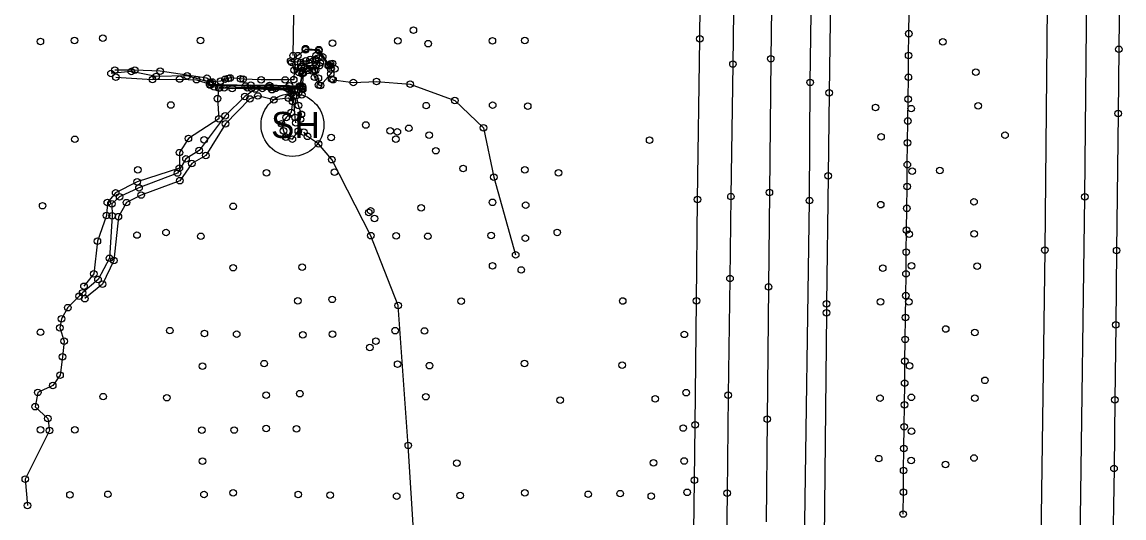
# Model space of a CAD drawing. Extents: x 20503438 to 20508873, y 7964251 to 7984667.
# Drawn here: x 20506435.8 to 20506772.2, y 7973039.7 to 7973190.9 of the extents above; entities that cross this region are included whole.
import ezdxf

# ---------------------------------------------------------------- set-up
doc = ezdxf.new("R2010")
doc.units = 0
for name, color, linetype in [('SurBreakLine', 7, 'Continuous'), ('SurConcreteSlab', 7, 'Continuous'), ('SurDrainageArrowDown', 7, 'Continuous'), ('SurDrainageArrowUp', 7, 'Continuous'), ('SurEdgeRoadPaved', 7, 'Continuous'), ('SurEdgeShoulderPaved', 7, 'Continuous'), ('SurGuardPost', 7, 'Continuous'), ('SurNaturalCells', 7, 'Continuous'), ('SurPointsNonDTM', 7, 'Continuous'), ('SurSurveyPoints', 7, 'Continuous')]:
    doc.layers.add(name, color=color, linetype=linetype)

msp = doc.modelspace()

# ---------------------------------------------------------------- linework, layer by layer
at = {"layer": 'SurBreakLine'}
for points in [[(20506693.93, 7974172.3), (20506703.16, 7974103.94), (20506708.65, 7974061.23), (20506717.15, 7973987.75), (20506724.71, 7973915.62), (20506727.66, 7973879.07), (20506730.35, 7973842.27), (20506733.65, 7973807.54), (20506740.64, 7973700.69), (20506742.76, 7973663.23), (20506744.46, 7973628.25), (20506747.41, 7973556.42), (20506749.27, 7973483.89), (20506749.75, 7973448.34), (20506750.05, 7973411.41), (20506750.05, 7973377.87), (20506750.04, 7973336.11), (20506749.88, 7973302.38), (20506749.66, 7973266.92), (20506748.75, 7973195.65), (20506748.06, 7973121.35), (20506742.68, 7972730.78)], [(20506658.64, 7973666.41), (20506660.5, 7973630.6), (20506663.28, 7973558.51), (20506664.28, 7973522.31), (20506665.15, 7973486.02), (20506665.41, 7973468.23), (20506665.94, 7973428.1), (20506666.1, 7973414.15), (20506666.08, 7973375.19), (20506665.8, 7973329.98), (20506665.6, 7973292.94), (20506665.39, 7973261.91), (20506665.32, 7973236.07), (20506664.68, 7973202.81), (20506664.37, 7973179.69), (20506663.97, 7973138.88), (20506663.74, 7973110.09), (20506663.33, 7973069.8), (20506662.94, 7973038.47)], [(20506522.96, 7973176.73), (20506524.98, 7973176.27), (20506526.63, 7973177.56), (20506526.85, 7973178.46), (20506526.35, 7973179.85), (20506525.65, 7973180.7), (20506523.8, 7973179.43), (20506520.91, 7973178.53), (20506520.17, 7973177.11), (20506520.35, 7973175.54), (20506521.34, 7973175.08)], [(20506518.16, 7973178.53), (20506518.9, 7973176.23), (20506518.77, 7973173.3), (20506516.16, 7973173.21), (20506508.85, 7973173.26), (20506503.37, 7973173.49), (20506502.57, 7973173.56), (20506499.34, 7973173.81), (20506498.72, 7973173.66), (20506497.8, 7973173.43), (20506496.43, 7973172.86), (20506493.91, 7973172.6), (20506492.3, 7973173.75), (20506477.98, 7973175.87), (20506470.27, 7973176.19), (20506464.13, 7973176.18)], [(20506521.69, 7973175.3), (20506523.09, 7973176.09), (20506524.37, 7973175.97), (20506525.13, 7973174.02), (20506526.3, 7973173.77), (20506526.31, 7973171.68), (20506526.93, 7973171.55), (20506530.06, 7973175.09), (20506531.32, 7973176.62), (20506530.58, 7973178.27), (20506529.6, 7973177.45)], [(20506464.51, 7973174.08), (20506475.68, 7973173.34), (20506483.96, 7973173.49), (20506489.08, 7973173.3), (20506493.12, 7973171.91), (20506505.64, 7973171.61)], [(20506496.15, 7973170.84), (20506497.55, 7973170.77), (20506500.01, 7973170.63), (20506505.91, 7973170.66), (20506509.19, 7973170.6), (20506513.19, 7973170.66), (20506516.65, 7973170.71), (20506521.52, 7973170.42), (20506521.69, 7973175.3)], [(20506521.34, 7973175.08), (20506520.56, 7973171.34), (20506517.52, 7973171.45), (20506511.33, 7973171.52), (20506505.64, 7973171.61)], [(20506496.15, 7973170.84), (20506495.95, 7973170.71), (20506495.49, 7973167.51), (20506495.9, 7973161.36), (20506486.62, 7973155.34), (20506483.93, 7973151.05), (20506483.86, 7973146.29), (20506470.96, 7973142.15), (20506464.42, 7973138.77), (20506461.88, 7973135.81), (20506461.59, 7973131.9), (20506458.84, 7973124.03), (20506457.76, 7973114.06), (20506454.75, 7973110.29)], [(20506518.36, 7973166.67), (20506517.16, 7973167.66), (20506512.67, 7973167.11), (20506507.85, 7973168.33), (20506505.42, 7973167.42), (20506497.98, 7973159.86), (20506491.97, 7973150.16), (20506487.69, 7973147.73), (20506483.98, 7973142.5), (20506472.18, 7973138.12), (20506467.71, 7973135.8), (20506465.25, 7973131.52), (20506463.87, 7973118.15), (20506460.39, 7973110.95), (20506454.98, 7973106.52)]]:
    msp.add_lwpolyline(points, dxfattribs=at)
for points in [[(20506521.37, 7973176.11), (20506523.67, 7973177.61), (20506525.7, 7973177.77), (20506525.43, 7973179.03), (20506523.53, 7973178.28), (20506520.99, 7973177.32)], [(20506515.63, 7973157.68), (20506516.37, 7973155.74), (20506518.35, 7973155.18), (20506520.17, 7973157.59), (20506520.86, 7973161.22), (20506521.11, 7973162.73), (20506520.23, 7973165.41), (20506519.61, 7973168.45), (20506521.27, 7973168.66), (20506521.45, 7973170.42), (20506520, 7973170.37), (20506518.16, 7973170.4), (20506518.11, 7973169.03), (20506518.36, 7973166.67), (20506518, 7973163.27), (20506516.49, 7973161.74), (20506515.08, 7973159.84)]]:
    msp.add_lwpolyline(points, close=True, dxfattribs=at)
at = {"layer": 'SurConcreteSlab'}
for points in [[(20506522.34, 7973182.75), (20506526.47, 7973182.46), (20506529.52, 7973177.7), (20506530, 7973178.08)], [(20506529.33, 7973177.59), (20506527.61, 7973180.27), (20506526.45, 7973182.14), (20506522.39, 7973182.41), (20506520.07, 7973180.63), (20506517.83, 7973178.98), (20506519.89, 7973178.74), (20506522.5, 7973179.05)], [(20506525.4, 7973176.09), (20506522.96, 7973176.68), (20506521.5, 7973175.42), (20506520.75, 7973171.38), (20506521.38, 7973171.31), (20506521.49, 7973171.14), (20506521.37, 7973170.6), (20506511.53, 7973170.91), (20506504.61, 7973170.78), (20506494.46, 7973171.12), (20506493.3, 7973171.62), (20506504, 7973171.37), (20506511.47, 7973171.43), (20506520.65, 7973171.12)]]:
    msp.add_lwpolyline(points, dxfattribs=at)
at = {"layer": 'SurDrainageArrowDown'}
for points in [[(20506704.79, 7973040.84), (20506704.87, 7973047.5), (20506704.95, 7973054.15), (20506705.03, 7973060.81), (20506705.11, 7973067.47), (20506705.19, 7973074.13), (20506705.27, 7973080.79), (20506705.35, 7973087.45), (20506705.44, 7973094.11), (20506705.52, 7973100.77), (20506705.6, 7973107.43), (20506705.68, 7973114.09), (20506705.76, 7973120.74), (20506705.84, 7973127.4), (20506705.92, 7973134.06), (20506706, 7973140.72), (20506706.08, 7973147.38), (20506706.16, 7973154.04), (20506706.24, 7973160.7), (20506706.32, 7973167.36), (20506706.4, 7973174.02), (20506706.48, 7973180.68), (20506706.56, 7973187.33), (20506706.64, 7973193.99)], [(20506519.44, 7973160.13), (20506519.18, 7973161.79), (20506518.68, 7973168.3), (20506518.97, 7973169.93)], [(20506582.39, 7972475.07), (20506582.65, 7972516.36), (20506588.45, 7972561.12), (20506586.2, 7972602.19), (20506585.43, 7972649.8), (20506585.69, 7972698.55), (20506585.31, 7972750.39), (20506584.27, 7972792.42), (20506582.67, 7972835.44), (20506573.89, 7972881.78), (20506561.94, 7972896), (20506559.1, 7972961.09), (20506557.3, 7973005.18), (20506553.75, 7973061.78), (20506550.66, 7973104.43), (20506542.34, 7973125.73), (20506530.42, 7973148.91), (20506526.31, 7973153.75), (20506522.97, 7973156.02), (20506521.88, 7973157.28)]]:
    msp.add_lwpolyline(points, dxfattribs=at)
at = {"layer": 'SurDrainageArrowUp'}
for points in [[(20506493.28, 7973172.48), (20506486.24, 7973174.47), (20506476.82, 7973174.29), (20506469.2, 7973175.79), (20506463, 7973175.19)], [(20506530.36, 7973173.49), (20506530.78, 7973173.29), (20506536.97, 7973172.44), (20506544.08, 7973172.74), (20506554.36, 7973171.96), (20506567.98, 7973166.95), (20506576.73, 7973158.64), (20506579.89, 7973143.58), (20506586.52, 7973119.89)], [(20506517.46, 7973170.19), (20506512.14, 7973170.24), (20506507.02, 7973170.45), (20506503.84, 7973168.2), (20506497.87, 7973162.27), (20506489.92, 7973151.73), (20506485.89, 7973149.13), (20506483.27, 7973144.83), (20506471.54, 7973140.28), (20506465.63, 7973137.57), (20506463.27, 7973135.47), (20506463.32, 7973131.8), (20506462.52, 7973118.83), (20506459.03, 7973112.33), (20506454.34, 7973108.32), (20506453.3, 7973107.31), (20506449.85, 7973103.78), (20506447.91, 7973100.39), (20506447.39, 7973097.64), (20506448.69, 7973093.53), (20506448.16, 7973088.79), (20506447.44, 7973083.19), (20506445.2, 7973080.07), (20506440.68, 7973077.94), (20506439.84, 7973073.58), (20506443.73, 7973069.96), (20506444.23, 7973066.33), (20506436.84, 7973051.49), (20506437.54, 7973043.48)]]:
    msp.add_lwpolyline(points, dxfattribs=at)
at = {"layer": 'SurEdgeRoadPaved'}
for points in [[(20506754.96, 7972745.65), (20506760.25, 7973137.58), (20506761.69, 7973282.93), (20506761.86, 7973353.9), (20506761.6, 7973424.82), (20506761.25, 7973458.85), (20506759.99, 7973532.54), (20506759.04, 7973564.75), (20506756.04, 7973636.58), (20506754.65, 7973665.96), (20506750.79, 7973733.72), (20506746.15, 7973800.82), (20506743.33, 7973835.58), (20506740.64, 7973867.92), (20506734.47, 7973936.28), (20506730.78, 7973972.39), (20506727.6, 7974001.68), (20506722.88, 7974042.92), (20506713.77, 7974114.92), (20506708.86, 7974151.42)], [(20506762.7, 7973701.3), (20506766.3, 7973628.52), (20506769.13, 7973555.56), (20506770.34, 7973519.36), (20506770.9, 7973482.77), (20506771.77, 7973445.1), (20506772.21, 7973371.49), (20506772.15, 7973360.12), (20506771.84, 7973291.7), (20506771.22, 7973237.95), (20506770.63, 7973182.56), (20506770.42, 7973162.97), (20506769.97, 7973121.19), (20506769.69, 7973098.56), (20506769.4, 7973075.66), (20506769.17, 7973054.72), (20506768.76, 7973026.07)], [(20506647.01, 7973660.24), (20506649.17, 7973617.44), (20506650.75, 7973577.56), (20506651.82, 7973545.13), (20506652.82, 7973509.46), (20506653.66, 7973463.03), (20506654.08, 7973436.98), (20506654.43, 7973400.6), (20506654.36, 7973389.39), (20506654.26, 7973372.56), (20506653.85, 7973322.78), (20506653.8, 7973301.82), (20506653.6, 7973256.77), (20506653.38, 7973225.81), (20506652.86, 7973178.07), (20506652.25, 7973137.64), (20506651.95, 7973112.67), (20506651.39, 7973077.12), (20506651.1, 7973047.21), (20506650.35, 7972994.14)], [(20506674.66, 7973031.32), (20506676.22, 7973136.41), (20506676.43, 7973172.48), (20506676.95, 7973207.59), (20506676.91, 7973240.58), (20506677.3, 7973275.95), (20506677.43, 7973310.72), (20506677.78, 7973346.61), (20506677.91, 7973379.86), (20506677.82, 7973415.88), (20506676.91, 7973485.63), (20506676.13, 7973520.88), (20506674, 7973590.15), (20506670.75, 7973659.42)], [(20506640.4, 7972996.37), (20506641.08, 7973051.14), (20506641.29, 7973068.03), (20506641.72, 7973105.85), (20506642.04, 7973136.76), (20506642.75, 7973185.74), (20506643.15, 7973227), (20506643.5, 7973266.97), (20506643.74, 7973295.62), (20506643.83, 7973313.1), (20506643.84, 7973316.04), (20506644.07, 7973368.4), (20506644.24, 7973389.25), (20506644.31, 7973418.66), (20506643.92, 7973441.49), (20506643.48, 7973476.06), (20506642.99, 7973504.63), (20506642.72, 7973513.53), (20506641.84, 7973543.02), (20506640.28, 7973592.41), (20506639.45, 7973610.26), (20506637.61, 7973650.43)]]:
    msp.add_lwpolyline(points, dxfattribs=at)
at = {"layer": 'SurEdgeShoulderPaved'}
msp.add_lwpolyline([(20506630.34, 7974152.37), (20506635.51, 7974114.13), (20506640.28, 7974077.28), (20506644.45, 7974039.3), (20506649.14, 7974001.32), (20506656.18, 7973935.68), (20506657.87, 7973918.76), (20506662.74, 7973866.45), (20506666.67, 7973820.29), (20506669.36, 7973783.88), (20506674.48, 7973709.53), (20506680.04, 7973598.16), (20506681.26, 7973562.05), (20506683.25, 7973489.61), (20506683.95, 7973452.45), (20506684.17, 7973413.27), (20506684.21, 7973379.49), (20506683.74, 7973332.17), (20506683.17, 7973234.7), (20506682.2, 7973169.26), (20506681.89, 7973143.95), (20506681.42, 7973104.97), (20506681.39, 7973102.17), (20506680.61, 7973023.61)], dxfattribs=at)
at = {"layer": 'SurGuardPost'}
msp.add_lwpolyline([(20506518.56, 7973180.63), (20506518.94, 7973199.21), (20506518.88, 7973206.16)], dxfattribs=at)
at = {"layer": 'SurNaturalCells'}
msp.add_circle((20506518.38, 7973159.49), 9.59, dxfattribs=at)
at = {"layer": 'SurPointsNonDTM'}
for centre in [(20506555.3, 7973188.4), (20506518.56, 7973180.63), (20506540.81, 7973159.48), (20506553.93, 7973158.47), (20506548.22, 7973157.71), (20506550.4, 7973157.39), (20506560.15, 7973156.37), (20506562.16, 7973151.64), (20506541.66, 7973132.77), (20506542.26, 7973133.27), (20506557.66, 7973134.21), (20506543.42, 7973130.97), (20506558.71, 7973096.67), (20506542.04, 7973091.64), (20506543.88, 7973093.54)]:
    msp.add_circle(centre, 1, dxfattribs=at)
at = {"layer": 'SurSurveyPoints'}
for centre in [(20506451.85, 7973185.25), (20506460.52, 7973185.96), (20506490.32, 7973185.24), (20506550.58, 7973185.17), (20506579.41, 7973185.15), (20506589.3, 7973185.22), (20506642.75, 7973185.74), (20506706.56, 7973187.33), (20506441.44, 7973184.96), (20506522.34, 7973182.75), (20506522.39, 7973182.41), (20506526.45, 7973182.14), (20506526.47, 7973182.46), (20506530.59, 7973184.42), (20506559.8, 7973184.28), (20506716.9, 7973184.81), (20506770.63, 7973182.56), (20506517.83, 7973178.98), (20506518.16, 7973178.53), (20506519.89, 7973178.74), (20506520.07, 7973180.63), (20506520.91, 7973178.53), (20506522.5, 7973179.05), (20506523.53, 7973178.28), (20506523.8, 7973179.43), (20506525.43, 7973179.03), (20506525.65, 7973180.7), (20506526.35, 7973179.85), (20506526.85, 7973178.46), (20506527.61, 7973180.27), (20506664.37, 7973179.69), (20506706.48, 7973180.68), (20506463, 7973175.19), (20506464.13, 7973176.18), (20506469.2, 7973175.79), (20506470.27, 7973176.19), (20506477.98, 7973175.87), (20506518.9, 7973176.23), (20506520.17, 7973177.11), (20506520.35, 7973175.54), (20506520.99, 7973177.32), (20506521.34, 7973175.08), (20506521.37, 7973176.11), (20506521.5, 7973175.42), (20506521.69, 7973175.3), (20506522.96, 7973176.73), (20506522.96, 7973176.68), (20506523.09, 7973176.09), (20506523.67, 7973177.61), (20506524.37, 7973175.97), (20506524.98, 7973176.27), (20506525.4, 7973176.09), (20506525.7, 7973177.77), (20506526.63, 7973177.56), (20506529.33, 7973177.59), (20506529.52, 7973177.7), (20506529.6, 7973177.45), (20506530, 7973178.08), (20506530.06, 7973176.52), (20506530.06, 7973175.09), (20506530.58, 7973178.27), (20506531.32, 7973176.62), (20506652.86, 7973178.07), (20506726.97, 7973175.57), (20506464.51, 7973174.08), (20506475.68, 7973173.34), (20506476.82, 7973174.29), (20506483.96, 7973173.49), (20506486.24, 7973174.47), (20506489.08, 7973173.3), (20506492.3, 7973173.75), (20506493.12, 7973171.91), (20506493.28, 7973172.48), (20506493.3, 7973171.62), (20506493.91, 7973172.6), (20506496.43, 7973172.86), (20506497.8, 7973173.43), (20506498.72, 7973173.66), (20506499.34, 7973173.81), (20506502.57, 7973173.56), (20506503.37, 7973173.49), (20506505.64, 7973171.61), (20506508.85, 7973173.26), (20506516.16, 7973173.21), (20506518.77, 7973173.3), (20506525.13, 7973174.02), (20506526.3, 7973173.77), (20506526.31, 7973171.68), (20506526.93, 7973171.55), (20506530.36, 7973173.49), (20506530.78, 7973173.29), (20506536.97, 7973172.44), (20506544.08, 7973172.74), (20506554.36, 7973171.96), (20506676.43, 7973172.48), (20506706.4, 7973174.02), (20506494.46, 7973171.12), (20506495.95, 7973170.71), (20506496.15, 7973170.84), (20506497.55, 7973170.77), (20506500.01, 7973170.63), (20506503.84, 7973168.2), (20506504, 7973171.37), (20506504.61, 7973170.78), (20506505.91, 7973170.66), (20506507.02, 7973170.45), (20506507.85, 7973168.33), (20506509.19, 7973170.6), (20506511.33, 7973171.52), (20506511.47, 7973171.43), (20506511.53, 7973170.91), (20506512.14, 7973170.24), (20506513.19, 7973170.66), (20506516.65, 7973170.71), (20506517.46, 7973170.19), (20506517.52, 7973171.45), (20506518.11, 7973169.03), (20506518.16, 7973170.4), (20506518.68, 7973168.3), (20506518.97, 7973169.93), (20506519.61, 7973168.45), (20506520, 7973170.37), (20506520.56, 7973171.34), (20506520.65, 7973171.12), (20506520.75, 7973171.38), (20506521.27, 7973168.66), (20506521.37, 7973170.6), (20506521.38, 7973171.31), (20506521.45, 7973170.42), (20506521.49, 7973171.14), (20506521.52, 7973170.42), (20506682.2, 7973169.26), (20506481.29, 7973165.58), (20506495.49, 7973167.51), (20506505.42, 7973167.42), (20506512.67, 7973167.11), (20506517.16, 7973167.66), (20506518.36, 7973166.67), (20506520.23, 7973165.41), (20506559.24, 7973165.38), (20506567.98, 7973166.95), (20506579.5, 7973165.51), (20506590.2, 7973165.25), (20506706.32, 7973167.36), (20506727.68, 7973165.3), (20506497.87, 7973162.27), (20506516.49, 7973161.74), (20506518, 7973163.27), (20506519.18, 7973161.79), (20506521.11, 7973162.73), (20506696.4, 7973164.8), (20506707.28, 7973164.47), (20506770.42, 7973162.97), (20506495.9, 7973161.36), (20506497.98, 7973159.86), (20506515.08, 7973159.84), (20506519.44, 7973160.13), (20506520.86, 7973161.22), (20506576.73, 7973158.64), (20506706.24, 7973160.7), (20506451.97, 7973155.12), (20506486.62, 7973155.34), (20506491.41, 7973154.96), (20506515.63, 7973157.68), (20506516.37, 7973155.74), (20506518.35, 7973155.18), (20506520.17, 7973157.59), (20506521.88, 7973157.28), (20506522.97, 7973156.02), (20506530.21, 7973155.69), (20506549.92, 7973155.16), (20506627.42, 7973154.86), (20506698.05, 7973155.86), (20506735.9, 7973156.37), (20506489.92, 7973151.73), (20506526.31, 7973153.75), (20506706.16, 7973154.04), (20506483.93, 7973151.05), (20506485.89, 7973149.13), (20506491.97, 7973150.16), (20506530.42, 7973148.91), (20506471.22, 7973145.82), (20506483.27, 7973144.83), (20506483.86, 7973146.29), (20506487.69, 7973147.73), (20506510.47, 7973144.88), (20506531.19, 7973145.07), (20506570.46, 7973146.22), (20506589.33, 7973145.78), (20506599.57, 7973144.92), (20506706.08, 7973147.38), (20506707.59, 7973145.41), (20506716, 7973145.59), (20506470.96, 7973142.15), (20506483.98, 7973142.5), (20506579.89, 7973143.58), (20506681.89, 7973143.95), (20506464.42, 7973138.77), (20506471.54, 7973140.28), (20506472.18, 7973138.12), (20506663.97, 7973138.88), (20506706, 7973140.72), (20506442.13, 7973134.87), (20506461.88, 7973135.81), (20506463.27, 7973135.47), (20506465.63, 7973137.57), (20506467.71, 7973135.8), (20506500.28, 7973134.68), (20506579.42, 7973135.89), (20506589.58, 7973135.04), (20506642.04, 7973136.76), (20506652.25, 7973137.64), (20506676.22, 7973136.41), (20506697.96, 7973135.18), (20506726.43, 7973136.07), (20506760.25, 7973137.58), (20506461.59, 7973131.9), (20506463.32, 7973131.8), (20506465.25, 7973131.52), (20506705.92, 7973134.06), (20506470.93, 7973125.92), (20506479.79, 7973126.72), (20506490.39, 7973125.54), (20506542.34, 7973125.73), (20506550.02, 7973125.71), (20506559.72, 7973125.54), (20506579.05, 7973125.79), (20506589.47, 7973124.95), (20506599.23, 7973126.73), (20506705.84, 7973127.4), (20506706.61, 7973126.16), (20506726.49, 7973126.28), (20506458.84, 7973124.03), (20506748.06, 7973121.35), (20506769.97, 7973121.19), (20506462.52, 7973118.83), (20506463.87, 7973118.15), (20506586.52, 7973119.89), (20506705.76, 7973120.74), (20506500.27, 7973115.96), (20506521.33, 7973116.15), (20506579.49, 7973116.51), (20506588.24, 7973115.27), (20506698.57, 7973115.85), (20506707.34, 7973116.51), (20506727.37, 7973116.45), (20506457.76, 7973114.06), (20506459.03, 7973112.33), (20506651.95, 7973112.67), (20506705.68, 7973114.09), (20506454.34, 7973108.32), (20506454.75, 7973110.29), (20506460.39, 7973110.95), (20506663.74, 7973110.09), (20506453.3, 7973107.31), (20506454.98, 7973106.52), (20506520.01, 7973105.83), (20506530.51, 7973106.3), (20506550.66, 7973104.43), (20506569.92, 7973105.78), (20506619.2, 7973105.81), (20506641.72, 7973105.85), (20506681.42, 7973104.97), (20506697.87, 7973105.52), (20506705.6, 7973107.43), (20506706.57, 7973105.58), (20506449.85, 7973103.78), (20506681.39, 7973102.17), (20506447.39, 7973097.64), (20506447.91, 7973100.39), (20506705.52, 7973100.77), (20506769.69, 7973098.56), (20506441.48, 7973096.26), (20506480.93, 7973096.77), (20506491.5, 7973095.92), (20506501.36, 7973095.71), (20506521.57, 7973095.5), (20506530.6, 7973095.7), (20506549.73, 7973096.76), (20506638.01, 7973095.63), (20506717.79, 7973097.27), (20506726.68, 7973096.21), (20506448.69, 7973093.53), (20506705.44, 7973094.11), (20506448.16, 7973088.79), (20506490.96, 7973085.92), (20506509.72, 7973086.71), (20506550.49, 7973086.53), (20506560.2, 7973086.09), (20506589.2, 7973086.73), (20506619.03, 7973086.25), (20506705.35, 7973087.45), (20506706.78, 7973086.02), (20506447.44, 7973083.19), (20506705.27, 7973080.79), (20506729.78, 7973081.61), (20506440.68, 7973077.94), (20506445.2, 7973080.07), (20506520.61, 7973077.55), (20506638.58, 7973077.85), (20506460.59, 7973076.65), (20506480.05, 7973076.32), (20506510.33, 7973077.08), (20506559.08, 7973076.62), (20506600.11, 7973075.58), (20506629.15, 7973075.97), (20506651.39, 7973077.12), (20506697.74, 7973076.17), (20506705.19, 7973074.13), (20506707.3, 7973076.43), (20506726.72, 7973076.21), (20506769.4, 7973075.66), (20506439.84, 7973073.58), (20506443.73, 7973069.96), (20506641.29, 7973068.03), (20506663.33, 7973069.8), (20506705.11, 7973067.47), (20506441.45, 7973066.49), (20506444.23, 7973066.33), (20506451.96, 7973066.53), (20506490.74, 7973066.42), (20506500.57, 7973066.46), (20506510.36, 7973066.9), (20506519.59, 7973066.8), (20506637.69, 7973067.07), (20506707.34, 7973066.08), (20506553.75, 7973061.78), (20506705.03, 7973060.81), (20506697.34, 7973057.74), (20506726.43, 7973057.93), (20506490.95, 7973056.98), (20506568.57, 7973056.37), (20506628.62, 7973056.45), (20506637.93, 7973057.01), (20506704.95, 7973054.15), (20506707.27, 7973057.16), (20506717.75, 7973055.95), (20506769.17, 7973054.72), (20506436.84, 7973051.49), (20506641.08, 7973051.14), (20506500.29, 7973047.28), (20506589.32, 7973047.3), (20506638.85, 7973047.46), (20506651.1, 7973047.21), (20506704.87, 7973047.5), (20506450.47, 7973046.71), (20506462.07, 7973046.86), (20506491.39, 7973046.83), (20506520.17, 7973046.83), (20506529.92, 7973046.6), (20506550.2, 7973046.29), (20506569.58, 7973046.49), (20506608.69, 7973046.86), (20506618.42, 7973047.07), (20506627.92, 7973046.26), (20506437.54, 7973043.48), (20506704.79, 7973040.84)]:
    msp.add_circle(centre, 1, dxfattribs=at)

# ---------------------------------------------------------------- texts
at = {"layer": 'SurNaturalCells'}
msp.add_text('SH', height=7.995, rotation=360, dxfattribs=at).set_placement((20506511.86, 7973155.49))

doc.saveas('drawing.dxf')
